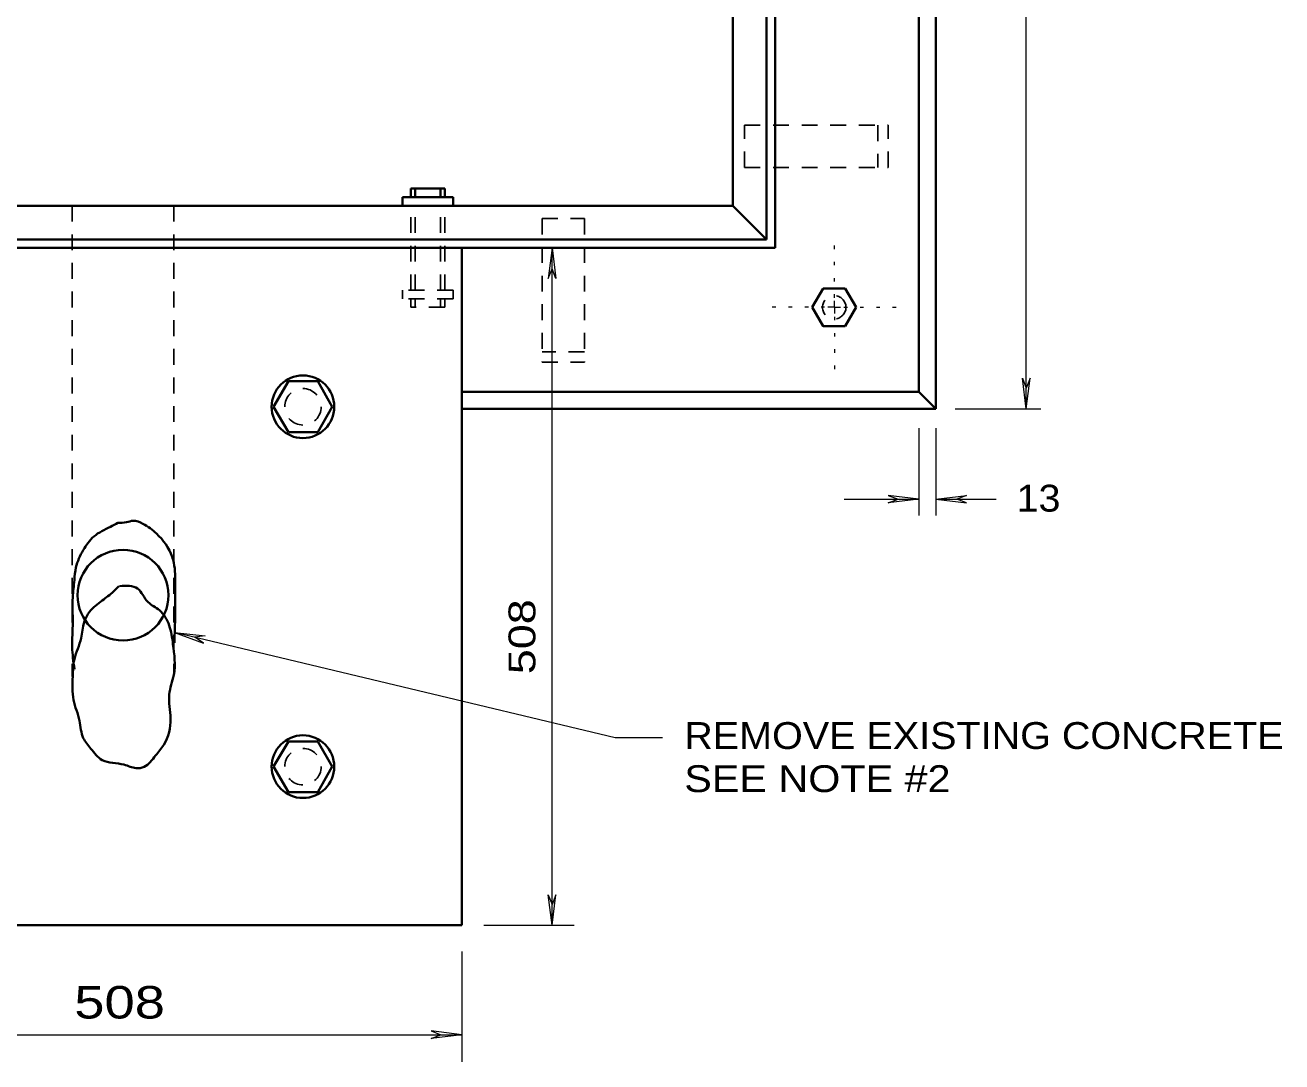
# Model space of a CAD drawing. Extents: x 312583 to 312853, y 144419 to 144586.
# Drawn here: x 312658.32 to 312693.88, y 144526.11 to 144555.44 of the extents above; entities that cross this region are included whole.
import ezdxf
from ezdxf.enums import TextEntityAlignment as Align

# ---------------------------------------------------------------- set-up
doc = ezdxf.new("R2010")
doc.units = 0
doc.header["$LTSCALE"] = 0.3
doc.linetypes.add('DOTTED', pattern=[1.5, 0.3, -1.2])
doc.linetypes.add('SHORT_DASHED', pattern=[2.7, 1.5, -1.2])
doc.layers.add('1', color=7, linetype='Continuous', lineweight=40)
doc.layers.add('2', color=7, linetype='Continuous', lineweight=13)

msp = doc.modelspace()

# ---------------------------------------------------------------- linework, layer by layer
at = {"layer": '1'}
for p, q in [((312684.0888, 144573.3329), (312684.0888, 144544.5829)), ((312678.3388, 144558.9196), (312678.3388, 144550.3329)), ((312670.1891, 144550.8159), (312669.2308, 144550.8159)), ((312669.2308, 144550.8159), (312669.2308, 144550.5706)), ((312669.3535, 144550.8159), (312669.3535, 144550.5706)), ((312670.0665, 144550.8159), (312670.0665, 144550.5706)), ((312670.1891, 144550.8159), (312670.1891, 144550.5706)), ((312670.4268, 144550.5706), (312668.9931, 144550.5706)), ((312668.9931, 144550.5706), (312668.9931, 144550.3329)), ((312670.4268, 144550.5706), (312670.4268, 144550.3329)), ((312678.3388, 144550.3329), (312679.2971, 144549.3746)), ((312642.8805, 144549.3746), (312679.2971, 144549.3746)), ((312642.6351, 144549.1369), (312679.5348, 144549.1369)), ((312670.6721, 144549.1369), (312670.6721, 144529.9703)), ((312680.8995, 144547.9946), (312680.5851, 144547.4579)), ((312681.5205, 144547.9946), (312680.8995, 144547.9946)), ((312681.8348, 144547.4579), (312681.5205, 144547.9946)), ((312681.8348, 144547.4579), (312681.5205, 144546.9213)), ((312665.3438, 144544.6443), (312665.7655, 144545.3649)), ((312665.7655, 144545.3649), (312666.5935, 144545.3649)), ((312666.5935, 144545.3649), (312667.0075, 144544.6443)), ((312670.6721, 144545.0659), (312683.6058, 144545.0659)), ((312684.0888, 144544.5829), (312683.6058, 144545.0659)), ((312665.3438, 144544.6443), (312665.7655, 144543.9236)), ((312670.6721, 144544.5829), (312684.0888, 144544.5829)), ((312665.3438, 144534.4629), (312665.7655, 144535.1759)), ((312665.7655, 144535.1759), (312666.5935, 144535.1759)), ((312666.5935, 144535.1759), (312667.0075, 144534.4629)), ((312665.3438, 144534.4629), (312665.7655, 144533.7423))]:
    msp.add_line(p, q, dxfattribs=at)
at = {"layer": '1', "linetype": 'SHORT_DASHED', "lineweight": 25}
for p, q in [((312678.6685, 144551.4139), (312678.6685, 144552.6099)), ((312678.6685, 144552.6099), (312682.7395, 144552.6099)), ((312682.4405, 144552.6099), (312682.4405, 144551.4139)), ((312682.7395, 144551.4139), (312682.7395, 144552.6099)), ((312678.6685, 144551.4139), (312682.7395, 144551.4139)), ((312659.6475, 144550.3329), (312659.6475, 144537.0083)), ((312662.5225, 144550.3329), (312662.5225, 144537.0083)), ((312669.2308, 144547.9409), (312669.2308, 144550.3329)), ((312669.3535, 144547.9409), (312669.3535, 144550.3329)), ((312670.0665, 144547.9409), (312670.0665, 144550.3329)), ((312670.1891, 144547.9409), (312670.1891, 144550.3329)), ((312672.9415, 144549.9726), (312674.1451, 144549.9726)), ((312672.9415, 144549.9726), (312672.9415, 144545.9093)), ((312674.1451, 144549.9726), (312674.1451, 144545.9093)), ((312670.4268, 144547.9409), (312668.9931, 144547.9409)), ((312668.9931, 144547.6956), (312668.9931, 144547.9409)), ((312670.4268, 144547.6956), (312670.4268, 144547.9409)), ((312670.4268, 144547.6956), (312668.9931, 144547.6956)), ((312669.2308, 144547.4579), (312669.2308, 144547.6956)), ((312670.1891, 144547.4579), (312669.2308, 144547.4579)), ((312669.3535, 144547.4579), (312669.3535, 144547.6956)), ((312670.0665, 144547.4579), (312670.0665, 144547.6956)), ((312670.1891, 144547.4579), (312670.1891, 144547.6956)), ((312674.1451, 144546.2006), (312672.9415, 144546.2006)), ((312672.9415, 144545.9093), (312674.1451, 144545.9093))]:
    msp.add_line(p, q, dxfattribs=at)
at = {"layer": '1'}
for points in [[(312638.5641, 144572.8576), (312683.6058, 144572.8576), (312683.6058, 144545.0659)], [(312642.6351, 144568.7789), (312679.5348, 144568.7789), (312679.5348, 144549.1369)], [(312642.8805, 144568.5413), (312679.2971, 144568.5413), (312679.2971, 144549.3746)], [(312643.8388, 144567.5829), (312643.8388, 144550.3329), (312678.3388, 144550.3329)], [(312651.5055, 144549.1369), (312651.5055, 144529.9703), (312670.6721, 144529.9703)], [(312681.5205, 144546.9213), (312680.8995, 144546.9213), (312680.5851, 144547.4579)], [(312665.7655, 144543.9236), (312666.5935, 144543.9236), (312667.0075, 144544.6443)], [(312665.7655, 144533.7423), (312666.5935, 144533.7423), (312667.0075, 144534.4629)]]:
    msp.add_lwpolyline(points, dxfattribs=at)
at = {"layer": '1', "linetype": 'SHORT_DASHED', "lineweight": 25}
for centre, radius in [((312681.21, 144547.4579), 0.3301), ((312666.1766, 144544.6433), 0.5157), ((312666.1766, 144534.4601), 0.5157)]:
    msp.add_circle(centre, radius, dxfattribs=at)
at = {"layer": '1'}
for centre, radius in [((312666.1766, 144544.6433), 0.8865), ((312661.085, 144539.3121), 1.2842), ((312666.1766, 144534.4601), 0.8865)]:
    msp.add_circle(centre, radius, dxfattribs=at)
for points in [[(312660.9431, 144541.3553), (312660.7285, 144541.2479), (312660.2608, 144540.9719), (312659.9618, 144540.5886), (312659.7548, 144540.0979), (312659.7088, 144539.7376), (312659.6628, 144539.2469), (312659.6628, 144538.5416), (312659.6475, 144537.8439), (312659.7088, 144537.2229)], [(312660.9431, 144541.3553), (312661.1808, 144541.3783), (312661.3725, 144541.4166), (312661.6485, 144541.3323), (312662.0318, 144541.0563), (312662.4765, 144540.3969), (312662.5225, 144540.2283), (312662.5608, 144539.5843), (312662.5608, 144538.7563), (312662.5378, 144537.9666)], [(312660.9661, 144539.5689), (312660.8128, 144539.4156), (312660.4985, 144539.1626), (312660.1381, 144538.8406), (312659.9848, 144538.5416), (312659.9005, 144538.0969), (312659.7088, 144537.4989), (312659.6628, 144537.0083), (312659.6858, 144536.3489), (312659.8545, 144535.7586), (312659.9618, 144535.2679), (312660.1765, 144534.9689), (312660.4985, 144534.6469), (312661.1118, 144534.5166), (312661.4568, 144534.4169), (312661.6868, 144534.4553), (312661.8555, 144534.5856), (312662.0088, 144534.7773), (312662.2388, 144535.0763), (312662.4305, 144535.8199), (312662.3921, 144536.5023), (312662.5225, 144537.0543), (312662.4995, 144537.9283), (312662.3921, 144538.4573), (312662.1161, 144538.8866), (312661.7941, 144539.1166), (312661.4951, 144539.4999), (312660.9891, 144539.5689)]]:
    msp.add_spline(points, degree=3, dxfattribs=at)
at = {"layer": '2'}
for p, q in [((312686.6418, 144544.5829), (312686.6418, 144573.3329)), ((312673.2251, 144549.1369), (312673.1178, 144548.2706)), ((312673.2251, 144529.9703), (312673.2251, 144549.1369)), ((312673.2251, 144549.1369), (312673.3325, 144548.2706)), ((312673.1178, 144548.2706), (312673.2251, 144548.5466)), ((312673.3325, 144548.2706), (312673.2251, 144548.5466)), ((312681.2138, 144547.4579), (312681.0298, 144547.4579)), ((312681.2138, 144547.4579), (312681.2138, 144547.6419)), ((312681.2138, 144547.4579), (312681.3901, 144547.4579)), ((312681.2138, 144547.4579), (312681.2138, 144547.2816)), ((312686.5345, 144545.4493), (312686.6418, 144545.1733)), ((312686.6418, 144544.5829), (312686.5345, 144545.4493)), ((312686.7491, 144545.4493), (312686.6418, 144545.1733)), ((312686.6418, 144544.5829), (312686.7491, 144545.4493)), ((312684.6331, 144544.5829), (312687.0558, 144544.5829)), ((312683.6058, 144544.0386), (312683.6058, 144541.5699)), ((312684.0888, 144544.0386), (312684.0888, 144541.5699)), ((312682.7395, 144542.1373), (312683.0155, 144542.0299)), ((312683.6058, 144542.0299), (312682.7395, 144542.1373)), ((312684.0888, 144542.0299), (312684.9551, 144542.1373)), ((312684.9551, 144542.1373), (312684.6791, 144542.0299)), ((312681.4898, 144542.0299), (312683.6058, 144542.0299)), ((312682.7395, 144541.9226), (312683.0155, 144542.0299)), ((312683.6058, 144542.0299), (312682.7395, 144541.9226)), ((312684.0888, 144542.0299), (312685.7908, 144542.0299)), ((312684.0888, 144542.0299), (312684.9551, 144541.9226)), ((312684.9551, 144541.9226), (312684.6791, 144542.0299)), ((312662.5455, 144538.2579), (312663.3658, 144537.9513)), ((312662.5455, 144538.2579), (312663.4118, 144538.1583)), ((312663.4118, 144538.1583), (312663.1205, 144538.1199)), ((312663.3658, 144537.9513), (312663.1205, 144538.1199)), ((312673.1178, 144530.8366), (312673.2251, 144530.5606)), ((312673.2251, 144529.9703), (312673.1178, 144530.8366)), ((312673.3325, 144530.8366), (312673.2251, 144530.5606)), ((312673.2251, 144529.9703), (312673.3325, 144530.8366)), ((312671.2931, 144529.9703), (312673.8538, 144529.9703)), ((312670.6721, 144529.2266), (312670.6721, 144526.1063)), ((312651.5055, 144526.8729), (312670.6721, 144526.8729)), ((312669.8058, 144526.9803), (312670.0818, 144526.8729)), ((312670.6721, 144526.8729), (312669.8058, 144526.9803)), ((312669.8058, 144526.7656), (312670.0818, 144526.8729)), ((312670.6721, 144526.8729), (312669.8058, 144526.7656))]:
    msp.add_line(p, q, dxfattribs=at)
at = {"layer": '2', "linetype": 'DOTTED'}
for p, q in [((312681.2138, 144547.7263), (312681.2138, 144549.5279)), ((312680.9378, 144547.4579), (312679.1438, 144547.4579)), ((312681.4821, 144547.4579), (312683.2761, 144547.4579)), ((312681.2138, 144547.1896), (312681.2138, 144545.3879))]:
    msp.add_line(p, q, dxfattribs=at)
at = {"layer": '2'}
msp.add_lwpolyline([(312676.3531, 144535.2756), (312675.0115, 144535.2756), (312662.5455, 144538.2579)], dxfattribs=at)

# ---------------------------------------------------------------- texts
for s, width, p in [('13 ', 1.1, (312686.3679, 144541.6771)), ('REMOVE EXISTING CONCRETE', 1.1, (312676.9665, 144534.9603)), ('SEE NOTE #2', 1.15, (312676.9665, 144533.7403))]:
    msp.add_text(s, height=0.76, dxfattribs=dict(at, width=width)).set_placement(p)
at = {"layer": '2', "width": 1.25}
msp.add_text('508 ', height=0.76, rotation=90, dxfattribs=at).set_placement((312672.7533, 144537.0762))
msp.add_text('508 ', height=0.92, dxfattribs=at).set_placement((312661.2024, 144527.3329), align=Align.CENTER)

doc.saveas('drawing.dxf')
